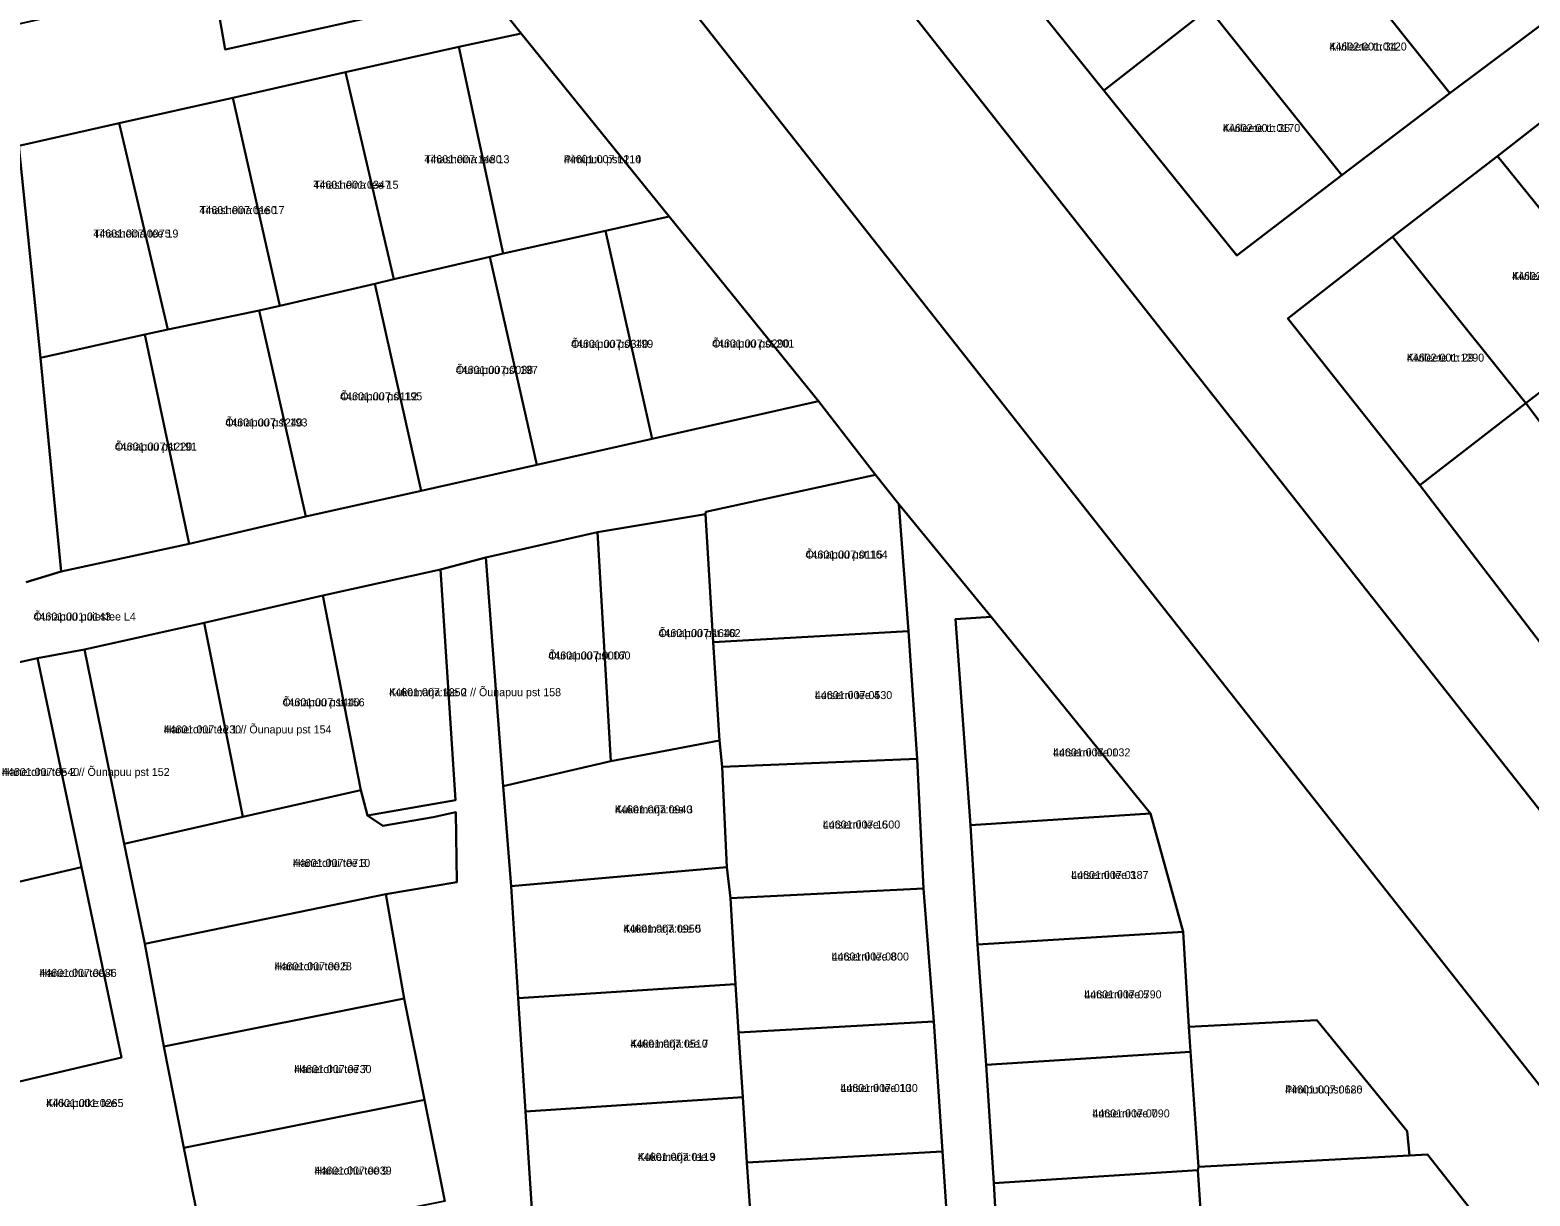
# Model space of a CAD drawing. Extents: x 551843 to 558501, y 6589003 to 6595718.
# Drawn here: x 554097.3 to 554378.5, y 6593355.7 to 6593574.5 of the extents above; entities that cross this region are included whole.
import ezdxf

# ---------------------------------------------------------------- set-up
doc = ezdxf.new("R2010")
doc.units = 0
for name, color, linetype in [('L_AADRESS', 7, 'Continuous'), ('PIIR', 7, 'Continuous'), ('TUNNUS', 7, 'Continuous')]:
    doc.layers.add(name, color=color, linetype=linetype)

msp = doc.modelspace()

# ---------------------------------------------------------------- linework, layer by layer
at = {"layer": 'PIIR'}
for points in [[(554441.09, 6593299.31), (554261.19, 6593527.78), (554141.98, 6593679.18), (554122.61, 6593703.78), (554013.74, 6593842.05), (553788.87, 6594127.63), (553766.28, 6594156.32), (553814.68, 6594146.58), (553836.64, 6594118.69), (553980.12, 6593936.47), (554062.14, 6593832.31), (554258.75, 6593582.61), (554309.59, 6593518.04), (554467.93, 6593316.95)], [(553918.7, 6593842.58), (554046.25, 6593756.59), (554079.11, 6593727.32), (554141.98, 6593679.18), (554261.19, 6593527.78), (554441.09, 6593299.31)], [(554370.87, 6593348.86), (554359.29, 6593363.51), (554355.96, 6593363.33), (554355.52, 6593367.92), (554338.59, 6593388.74), (554314.55, 6593387.45), (554313.51, 6593405.27), (554307.37, 6593427.52), (554277.53, 6593464.41), (554260.2, 6593485.51), (554255.79, 6593491.05), (554245.13, 6593504.82), (554217.11, 6593539.51), (554189.38, 6593573.83), (554183.04, 6593581.77), (554168.4, 6593600.04), (554144.19, 6593629.98), (554124.2, 6593625.76), (554123.15, 6593631.73), (554118.48, 6593658.32), (554113.64, 6593656.6), (554110.23, 6593671.81), (554096.69, 6593688.65)], [(554467.93, 6593316.95), (554309.59, 6593518.04), (554258.75, 6593582.61), (554273.69, 6593594.18), (554298.61, 6593563.13), (554323.57, 6593532.14), (554343.27, 6593547.24), (554363.47, 6593562.61), (554383.58, 6593577.63)], [(554092.95, 6593575.11), (554130.03, 6593583.41), (554131.6, 6593583.76), (554133.87, 6593570.82), (554183.04, 6593581.77), (554189.38, 6593573.83), (554177.67, 6593571.34), (554156.44, 6593566.58), (554135.34, 6593561.74), (554113.99, 6593556.97), (554095.21, 6593552.75), (554099.27, 6593512.97), (554103.1, 6593472.87), (554096.58, 6593470.92)], [(554096.58, 6593470.92), (554103.1, 6593472.87), (554127.12, 6593478.07), (554149, 6593483.19), (554170.65, 6593488.05), (554192.29, 6593492.9), (554213.94, 6593497.75), (554245.13, 6593504.82), (554255.79, 6593491.05), (554223.98, 6593484.08), (554223.95, 6593483.63), (554203.69, 6593480.29), (554182.77, 6593475.53), (554174.24, 6593473.28), (554152.18, 6593468.41), (554129.94, 6593463.25), (554107.5, 6593458.23), (554098.69, 6593456.61), (554077.1, 6593451.82)], [(554269.98, 6593339.69), (554268.35, 6593364.09), (554266.75, 6593388.49), (554264.83, 6593413.42), (554263.62, 6593437.73), (554261.99, 6593461.69), (554260.2, 6593485.51), (554277.53, 6593464.41), (554270.81, 6593463.92), (554273.65, 6593425.28), (554274.95, 6593402.9), (554276.55, 6593380.37), (554278, 6593358.18), (554279.27, 6593335.87)], [(554175.06, 6593354.75), (554171.26, 6593373.78), (554167.47, 6593392.81), (554164.03, 6593412.36), (554177.33, 6593414.61), (554177.12, 6593427.77), (554172.88, 6593426.84), (554163.41, 6593425.2), (554160.54, 6593427.15), (554177.08, 6593429.97), (554174.24, 6593473.28), (554182.77, 6593475.53), (554186.01, 6593432.64), (554187.53, 6593413.87), (554188.81, 6593392.85), (554190.19, 6593371.62), (554191.59, 6593350.39)], [(554034.35, 6593342.28), (554026.31, 6593360.98), (554045.99, 6593366.02), (554068.74, 6593370.62), (554091.86, 6593376.39), (554114.45, 6593381.74), (554106.93, 6593417.46), (554098.69, 6593456.61), (554107.5, 6593458.23), (554114.96, 6593421.78), (554118.81, 6593403.05), (554122.35, 6593383.82), (554126.15, 6593364.79), (554129.94, 6593345.76)]]:
    msp.add_lwpolyline(points, dxfattribs=at)
for points in [[(554476.4, 6593580.68), (554452, 6593612.33), (554432.2, 6593597.02), (554412.35, 6593581.81), (554392.11, 6593566.18), (554372.43, 6593550.81), (554352.76, 6593535.68), (554333.11, 6593520.38), (554357.89, 6593489.06), (554382.05, 6593457.43), (554401.92, 6593472.27), (554421.53, 6593487.82), (554441.21, 6593503.19), (554461.03, 6593518.87), (554480.6, 6593534.15), (554500.31, 6593549.23)], [(554298.61, 6593563.13), (554273.69, 6593594.18), (554293.76, 6593609.72), (554318.34, 6593578.52)], [(554358.69, 6593609.46), (554383.58, 6593577.63), (554363.47, 6593562.61), (554338.52, 6593594.03)], [(554168.4, 6593600.04), (554183.04, 6593581.77), (554133.87, 6593570.82), (554131.6, 6593583.76), (554130.22, 6593591.59)], [(554338.52, 6593594.03), (554363.47, 6593562.61), (554343.27, 6593547.24), (554318.34, 6593578.52)], [(554318.34, 6593578.52), (554343.27, 6593547.24), (554323.57, 6593532.14), (554298.61, 6593563.13)], [(554186.02, 6593532.52), (554177.67, 6593571.34), (554189.38, 6593573.83), (554217.11, 6593539.51), (554205.21, 6593536.79)], [(554165.51, 6593527.73), (554156.44, 6593566.58), (554177.67, 6593571.34), (554186.02, 6593532.52), (554183.53, 6593531.94)], [(554135.34, 6593561.74), (554156.44, 6593566.58), (554165.51, 6593527.73), (554161.95, 6593526.88), (554144.1, 6593522.71)], [(554392.11, 6593566.18), (554417.34, 6593535.08), (554397.57, 6593519.71), (554372.43, 6593550.81)], [(554123.1, 6593518.31), (554113.99, 6593556.97), (554135.34, 6593561.74), (554144.1, 6593522.71), (554140.26, 6593521.84)], [(554113.99, 6593556.97), (554123.1, 6593518.31), (554118.83, 6593517.38), (554099.27, 6593512.97), (554095.21, 6593552.75)], [(554372.43, 6593550.81), (554397.57, 6593519.71), (554377.75, 6593504.49), (554352.76, 6593535.68)], [(554217.11, 6593539.51), (554245.13, 6593504.82), (554213.94, 6593497.75), (554205.21, 6593536.79)], [(554183.53, 6593531.94), (554186.02, 6593532.52), (554205.21, 6593536.79), (554213.94, 6593497.75), (554192.29, 6593492.9)], [(554352.76, 6593535.68), (554377.75, 6593504.49), (554357.89, 6593489.06), (554333.11, 6593520.38)], [(554192.29, 6593492.9), (554170.65, 6593488.05), (554161.95, 6593526.88), (554165.51, 6593527.73), (554183.53, 6593531.94)], [(554149, 6593483.19), (554140.26, 6593521.84), (554144.1, 6593522.71), (554161.95, 6593526.88), (554170.65, 6593488.05)], [(554140.26, 6593521.84), (554149, 6593483.19), (554127.12, 6593478.07), (554118.83, 6593517.38), (554123.1, 6593518.31)], [(554118.83, 6593517.38), (554127.12, 6593478.07), (554103.1, 6593472.87), (554099.27, 6593512.97)], [(554397.57, 6593519.71), (554421.53, 6593487.82), (554401.92, 6593472.27), (554377.75, 6593504.49)], [(554377.75, 6593504.49), (554401.92, 6593472.27), (554382.05, 6593457.43), (554357.89, 6593489.06)], [(554255.79, 6593491.05), (554260.2, 6593485.51), (554261.99, 6593461.69), (554225.35, 6593459.61), (554223.95, 6593483.63), (554223.98, 6593484.08)], [(554203.69, 6593480.29), (554223.95, 6593483.63), (554225.35, 6593459.61), (554226.56, 6593441.17), (554206.17, 6593437.3)], [(554186.01, 6593432.64), (554182.77, 6593475.53), (554203.69, 6593480.29), (554206.17, 6593437.3)], [(554177.08, 6593429.97), (554160.54, 6593427.15), (554159.34, 6593431.89), (554152.18, 6593468.41), (554174.24, 6593473.28)], [(554159.34, 6593431.89), (554137.22, 6593426.89), (554129.94, 6593463.25), (554152.18, 6593468.41)], [(554277.53, 6593464.41), (554307.37, 6593427.52), (554273.65, 6593425.28), (554270.81, 6593463.92)], [(554129.94, 6593463.25), (554137.22, 6593426.89), (554114.96, 6593421.78), (554107.5, 6593458.23)], [(554226.56, 6593441.17), (554225.35, 6593459.61), (554261.99, 6593461.69), (554263.62, 6593437.73), (554227.09, 6593436.24)], [(554077.1, 6593451.82), (554098.69, 6593456.61), (554106.93, 6593417.46), (554086.3, 6593412.62)], [(554187.53, 6593413.87), (554186.01, 6593432.64), (554206.17, 6593437.3), (554226.56, 6593441.17), (554227.09, 6593436.24), (554227.95, 6593417.44)], [(554227.95, 6593417.44), (554227.09, 6593436.24), (554263.62, 6593437.73), (554264.83, 6593413.42), (554228.62, 6593411.62)], [(554177.33, 6593414.61), (554164.03, 6593412.36), (554118.81, 6593403.05), (554114.96, 6593421.78), (554137.22, 6593426.89), (554159.34, 6593431.89), (554160.54, 6593427.15), (554163.41, 6593425.2), (554172.88, 6593426.84), (554177.12, 6593427.77)], [(554273.65, 6593425.28), (554307.37, 6593427.52), (554313.51, 6593405.27), (554274.95, 6593402.9)], [(554083.63, 6593411.96), (554086.3, 6593412.62), (554106.93, 6593417.46), (554114.45, 6593381.74), (554091.86, 6593376.39)], [(554227.95, 6593417.44), (554228.62, 6593411.62), (554229.54, 6593395.51), (554188.81, 6593392.85), (554187.53, 6593413.87)], [(554229.54, 6593395.51), (554228.62, 6593411.62), (554264.83, 6593413.42), (554266.75, 6593388.49), (554230.11, 6593386.41)], [(554118.81, 6593403.05), (554164.03, 6593412.36), (554167.47, 6593392.81), (554122.35, 6593383.82)], [(554274.95, 6593402.9), (554313.51, 6593405.27), (554314.55, 6593387.45), (554314.88, 6593382.8), (554276.55, 6593380.37)], [(554188.81, 6593392.85), (554229.54, 6593395.51), (554230.11, 6593386.41), (554230.91, 6593374.28), (554190.19, 6593371.62)], [(554122.35, 6593383.82), (554167.47, 6593392.81), (554171.26, 6593373.78), (554126.15, 6593364.79)], [(554230.91, 6593374.28), (554230.11, 6593386.41), (554266.75, 6593388.49), (554268.35, 6593364.09), (554231.71, 6593362.02)], [(554314.55, 6593387.45), (554338.59, 6593388.74), (554355.52, 6593367.92), (554355.96, 6593363.33), (554316.4, 6593361.22)], [(554314.88, 6593382.8), (554316.4, 6593361.22), (554316.26, 6593360.62), (554278, 6593358.18), (554276.55, 6593380.37)], [(554191.59, 6593350.39), (554190.19, 6593371.62), (554230.91, 6593374.28), (554231.71, 6593362.02), (554232.3, 6593353.05)], [(554175.06, 6593354.75), (554129.94, 6593345.76), (554126.15, 6593364.79), (554171.26, 6593373.78)], [(554232.3, 6593353.05), (554231.71, 6593362.02), (554268.35, 6593364.09), (554269.98, 6593339.69), (554233.34, 6593337.62)], [(554316.4, 6593361.22), (554355.96, 6593363.33), (554359.29, 6593363.51), (554370.87, 6593348.86), (554357.01, 6593347.99), (554357.18, 6593340.35), (554337.73, 6593339.18), (554317.72, 6593338.39), (554316.26, 6593360.62)], [(554316.26, 6593360.62), (554317.72, 6593338.39), (554279.27, 6593335.87), (554278, 6593358.18)]]:
    msp.add_lwpolyline(points, close=True, dxfattribs=at)

# ---------------------------------------------------------------- texts
at = {"layer": 'L_AADRESS'}
for s, p in [('Kivileete tn 34', (554340.91, 6593570.62)), ('Kivileete tn 36', (554320.94, 6593555.33)), ('Tihasheina tee 13', (554171.23, 6593549.48)), ('Pirnipuu pst 114', (554197.39, 6593549.48)), ('Tihasheina tee 15', (554150.43, 6593544.69)), ('Tihasheina tee 17', (554129.05, 6593539.93)), ('Tihasheina tee 19', (554109.16, 6593535.54)), ('Kivileete tn 27', (554375.16, 6593527.57)), ('Õunapuu pst 199', (554198.73, 6593514.85)), ('Õunapuu pst 201', (554225.17, 6593514.91)), ('Õunapuu pst 197', (554177.12, 6593509.97)), ('Kivileete tn 29', (554355.43, 6593512.26)), ('Õunapuu pst 195', (554155.45, 6593505)), ('Õunapuu pst 193', (554133.91, 6593500.1)), ('Õunapuu pst 191', (554113.2, 6593495.58)), ('Õunapuu pst 164', (554242.7, 6593475.33)), ('Õunapuu puiestee L4', (554097.95, 6593463.7)), ('Õunapuu pst 162', (554215.12, 6593460.59)), ('Õunapuu pst 160', (554194.47, 6593456.39)), ('Kukemarja tee 2 // Õunapuu pst 158', (554164.63, 6593449.5)), ('Lutserni tee 4', (554244.45, 6593448.96)), ('Õunapuu pst 156', (554144.64, 6593447.61)), ('Hanerohu tee 1 // Õunapuu pst 154', (554122.36, 6593442.52)), ('Lutserni tee 1', (554289.09, 6593438.21)), ('Hanerohu tee 2 // Õunapuu pst 152', (554092.02, 6593434.54)), ('Kukemarja tee 3', (554206.96, 6593427.52)), ('Lutserni tee 6', (554245.94, 6593424.68)), ('Hanerohu tee 3', (554146.57, 6593417.47)), ('Lutserni tee 3', (554292.5, 6593415.21)), ('Kukemarja tee 5', (554208.53, 6593405.15)), ('Hanerohu tee 5', (554143.13, 6593398.09)), ('Lutserni tee 8', (554247.58, 6593399.92)), ('Hanerohu tee 4', (554099.04, 6593396.85)), ('Lutserni tee 5', (554294.95, 6593392.82)), ('Kukemarja tee 7', (554209.86, 6593383.57)), ('Hanerohu tee 7', (554146.81, 6593378.8)), ('Lutserni tee 10', (554249.23, 6593375.25)), ('Kikkaputke tee', (554100.32, 6593372.44)), ('Pirnipuu pst 126', (554332.6, 6593374.98)), ('Lutserni tee 7', (554296.47, 6593370.49)), ('Kukemarja tee 9', (554211.25, 6593362.34)), ('Hanerohu tee 9', (554150.6, 6593359.77))]:
    msp.add_text(s, height=1.5, dxfattribs=at).set_placement(p)
at = {"layer": 'TUNNUS'}
for s, p in [('44602:001:0120', (554340.91, 6593570.62)), ('44602:001:0170', (554320.94, 6593555.33)), ('44601:007:1480', (554171.23, 6593549.48)), ('44601:007:1210', (554197.39, 6593549.48)), ('44601:001:0347', (554150.43, 6593544.69)), ('44601:007:0160', (554129.05, 6593539.93)), ('44601:007:0075', (554109.16, 6593535.54)), ('44602:001:0470', (554375.16, 6593527.57)), ('44601:007:0340', (554198.73, 6593514.85)), ('44601:007:0290', (554225.17, 6593514.91)), ('44602:001:1290', (554355.43, 6593512.26)), ('44601:007:0038', (554177.12, 6593509.97)), ('44601:007:0112', (554155.45, 6593505)), ('44601:007:1240', (554133.91, 6593500.1)), ('44601:007:1220', (554113.2, 6593495.58)), ('44601:007:0115', (554242.7, 6593475.33)), ('44601:001:0143', (554097.95, 6593463.7)), ('44601:007:1640', (554215.12, 6593460.59)), ('44601:007:0007', (554194.47, 6593456.39)), ('44601:007:1250', (554164.63, 6593449.5)), ('44601:007:0530', (554244.45, 6593448.96)), ('44601:007:1440', (554144.64, 6593447.61)), ('44601:007:1230', (554122.36, 6593442.52)), ('44601:007:0032', (554289.09, 6593438.21)), ('44601:007:0540', (554092.02, 6593434.54)), ('44601:007:0940', (554206.96, 6593427.52)), ('44601:007:1500', (554245.94, 6593424.68)), ('44601:007:0710', (554146.57, 6593417.47)), ('44601:007:0187', (554292.5, 6593415.21)), ('44601:007:0950', (554208.53, 6593405.15)), ('44601:007:0028', (554143.13, 6593398.09)), ('44601:007:0800', (554247.58, 6593399.92)), ('44601:007:0086', (554099.04, 6593396.85)), ('44601:007:0790', (554294.95, 6593392.82)), ('44601:007:0510', (554209.86, 6593383.57)), ('44601:007:0730', (554146.81, 6593378.8)), ('44601:007:0130', (554249.23, 6593375.25)), ('44601:001:0265', (554100.32, 6593372.44)), ('44601:007:0680', (554332.6, 6593374.98)), ('44601:007:0090', (554296.47, 6593370.49)), ('44601:007:0113', (554211.25, 6593362.34)), ('44601:007:0039', (554150.6, 6593359.77))]:
    msp.add_text(s, height=1.5, dxfattribs=at).set_placement(p)

doc.saveas('drawing.dxf')
